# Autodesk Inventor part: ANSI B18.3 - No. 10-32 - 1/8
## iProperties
Comments: To add or edit properties for Autodesk Inventor files, use iProperties.
Created: 2005-01
Part Number: ANSI B18.3 - No. 10-32 - 1/8
Vendor: Autodesk Inc.
Document SubType Name: Modeling
Designer: John Blackburn
Material: Default
Description: Hexagon Socket Button Head Cap Screw
Standard: ANSI B18.3
Alert: To add or edit properties for Autodesk Inventor files, use iProperties.
Control State: 0
Master: False
Checked Out: False
Shininess: 64.0
Length Units: 11272
Angle Units: 11279
Time Units: 11290
Mass Units: 11286
Length Display Precision: 3
Angle Display Precision: 2
Compacted: True
EGR: 4
Classification: un/spsc 31161501
Density: 0.0
Volumn: 0.0
Area: 0.0
PropertySet Name: Model Information
Author: John Blackburn
Revision Number: 8
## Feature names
1. Body [Revolution]
2. Slot [Extrusion]
3. Fillet1
4. Chamfer1
